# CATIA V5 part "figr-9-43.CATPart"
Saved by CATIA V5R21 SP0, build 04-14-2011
Part number: Part1
Bounding box of the stored display mesh (mm): x -60 to 60, y -70.327 to 65.87, z 0 to 125
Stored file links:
  D:\CATIA V5R21 E-RESOURCES\CATIA-V5R21\catia-v5r21-prt\c09-catia-v5r20-prt\c09-catia-v5r21-figr-9-43.CATPart
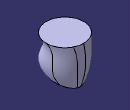
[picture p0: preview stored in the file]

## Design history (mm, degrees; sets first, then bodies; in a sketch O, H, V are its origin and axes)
Set1
  Plane1: type Offset, RefPlane xy-plane, Offset 125
Body1 (main body)
  Sketch1 on xy-plane, origin (0, 0, 0), H (1, 0, 0), V (0, 1, 0)
    ellipse A1 centre (0, 0) semi-axes 50, 30 rotation 270
    point P1 (30, 0)
    coincidence: P1 H, A1 P1
  Sketch2 on Plane1, origin (0, 0, 125), H (1, 0, 0), V (0, 1, 0)
    circle A1 centre (0, 0) radius 60
  Sketch3 on yz-plane, origin (0, 0, 0), H (0, 1, 0), V (0, 0, 1)
    arc A1 centre (-129.6632, 77.2731) radius 195.5761 from (50, 0) to (60, 125) ccw
    point P2 (50, 0)
    point P3 (60, 125)
    reference projected line E1 (-50, 0) -> (50, 0) from edge of Sketch1
    reference projected line E2 (-60, 125) -> (60, 125) from edge of Sketch2
    coincidence: P2 H, P2 E1, P3 E2
  Sketch4 on yz-plane, origin (0, 0, 0), H (0, 1, 0), V (0, 0, 1)
    spline S1 through (-50, 0) (-70, 40) (-50, 100) (-60, 125)
    reference projected line E1 (-60, 125) -> (60, 125) from edge of Sketch2
    reference projected line E2 (-50, 0) -> (50, 0) from edge of Sketch1
    point P1 (-60, 125)
    point P2 (-50, 0)
    coincidence: P1 E1, P2 E2
  Loft1: Sections (Sketch1; Sketch2), Guides (Sketch3; Sketch4)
